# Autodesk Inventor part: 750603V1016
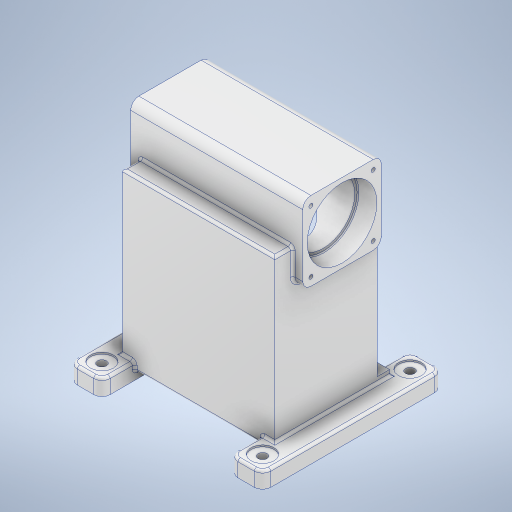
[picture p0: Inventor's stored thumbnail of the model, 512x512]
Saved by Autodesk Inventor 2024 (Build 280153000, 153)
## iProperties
Created: 2025-06
Part Number: 750603V1016
Material: 알루미늄 6061
Document SubType Name: Modeling
Designer: 11
Mass: 8009.62 g
Surface Area: 3457.08 cm^2
Volume: 2966.53 cm^3
Density: 2.7 g/cm^3
Appearance: 알루미늄 - 평지
Author: 11
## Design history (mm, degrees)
sketch "스케치1"
  geometry: L1 (-103, 70)-(103, 70); L2 (103, 70)-(103, -70); L3 (103, -70)-(-103, -70); L4 (-103, -70)-(-103, 70); L5 (103, -55)-(-86, -55); L6 (-86, -55)-(-86, -70); 4 further points
  constraints: 12 end point, 3 midpoint, 3 perpendicular, 2 parallel, 2 point on line, 1 horizontal, 1 horizontal alignment, 1 vertical alignment
  dimensions: "d0" = 206 distance of L2.end L3.end; "d1" = 140 distance of L1.end L2.end; "d8" = 15 distance between parallel lines of L3 L5; "d9" = 189 distance from line of point (-86, -62.5) L2
extrude "돌출1" new body sketch "스케치1" stored distance "d2" = 186; taper "d3" = 0 deg
sketch "스케치2"
  geometry: L1 (211, 180)-(-25, 180); L2 (-25, 180)-(-25, -40); L3 (-25, -40)-(211, -40); L4 (211, -40)-(211, 180); L5 (171, 180)-(171, -40); L6 (15, 180)-(15, -40); 3 further points
  constraints: 12 end point, 4 point on line, 3 perpendicular, 2 midpoint, 2 parallel, 1 horizontal, 1 horizontal alignment, 1 vertical alignment
  dimensions: "d4" = 236 distance of L2.end L3.end; "d10" = 220 distance of L3.end L1.start; "d11" = 40 distance between parallel lines of L2 L6; "d12" = 40 distance between parallel lines of L4 L5
extrude "돌출2" join sketch "스케치2" stored distance "d13" = 20; taper "d14" = 0 deg
sketch "스케치3"
  geometry: L1 (158, 38)-(158, -38); L2 (148, -48)-(72, -48); L3 (62, -38)-(62, 38); L4 (72, 48)-(148, 48); L5 (-113, -110)-(-113, 110) reference; L6 (-93, 70)-(103, 70) reference; L7 (103, 70)-(103, -55) reference; A1 r 10 centre (148, 38) between (158, 38) and (148, 48); A2 r 10 centre (148, -38) between (148, -48) and (158, -38); A3 r 10 centre (72, 38) between (72, 48) and (62, 38); A4 r 10 centre (72, -38) between (62, -38) and (72, -48); 8 further points
  constraints: 8 end point, 8 point on circle, 8 point on line, 8 tangent, 4 centre point, 3 midpoint, 3 perpendicular, 2 equal radius, 1 horizontal alignment, 1 vertical
  dimensions: "d15" = 271 distance between parallel lines of L5 L1; "d16" = 96 distance of point (158, 48) point (158, -48); "d17" = 96 distance of point (158, -48) point (62, -48); "d21" = 10 radius of A1 (derived); "d24" = 10 radius of A3 (derived)
extrude "돌출3" join sketch "스케치3" stored distance "d22" = 210; taper "d23" = 0 deg
node "작업 평면1"
sketch "스케치5"
  geometry: L1 (-12, 32)-(-12, 108) reference; L2 (198, 108)-(198, 32) reference; L3 (198, 22)-(198, 32) reference; L4 (198, 108)-(198, 118) reference; L5 (-12, 118)-(-12, 108) reference; L6 (-12, 32)-(-12, 22) reference; L7 (198, 70)-(-12, 70); L8 (-12, 70)-(-12, 27.5); L9 (11, 28.6)-(11, 31.5); L10 (11, 31.5)-(175, 31.5); L11 (175, 31.5)-(175, 28.6); L12 (186, 32)-(198, 32) reference; L13 (176.1, 27.5)-(198, 27.5); L14 (198, 70)-(198, 27.5); L15 (9.9, 27.5)-(-12, 27.5); L16 (-12, 32)-(0, 32) reference; A1 r 1.1 centre (9.9, 28.6) between (9.9, 27.5) and (11, 28.6); A2 r 1.1 centre (176.1, 28.6) between (175, 28.6) and (176.1, 27.5); 4 further points
  constraints: 16 end point, 5 midpoint, 4 perpendicular, 4 point on circle, 4 tangent, 2 centre point, 2 point on line, 1 equal radius, 1 parallel, 1 vertical
  dimensions: "d39" = 85 diameter of L15 L7; "d40" = 77 diameter of L10 L7; "d41" = 23 distance from line of L8 point (11, 30.05); "d42" = 23 horizontal distance of point (198, 27) point (175, 30.05); "d43" = 85 diameter of L13 L7; "d44" = 1.1 radius of A1 (derived)
revolve "회전2" sketch "스케치5" stored, may be unused: angle "d45" = 90 deg
sketch "스케치7"
  geometry: L1 (-86, -55)-(103, -55) reference; L2 (103, 70)-(-93, 70) reference; L3 (10, 70)-(10, -55); L4 (-113, 110)-(-113, -110) reference; L5 (10, -55)-(96, -55); L6 (96, -55)-(96, 47); L7 (96, 47)-(41, 47); L8 (41, 47)-(41, 62); L9 (40, 63)-(37, 63); L10 (37, 63)-(37, 63); L11 (34, 66)-(10, 66); A1 r 3 centre (34, 63) between (37, 63) and (34, 66); A2 r 1 centre (40, 62) between (41, 62) and (40, 63); 2 further points
  constraints: 16 end point, 6 perpendicular, 4 point on circle, 4 point on line, 4 tangent, 2 centre point, 1 vertical
  dimensions: "d68" = 123 distance between parallel lines of L4 L3; "d70" = 172 diameter of L6 L3; "d71" = 102 distance between parallel lines of L1 L7; "d72" = 16 distance between parallel lines of L7 L9; "d73" = 3 distance between parallel lines of L9 L11; "d74" = 62 diameter of L8 L3; "d75" = 54 diameter of L9.end L3; "d76" = 3 radius of A1 (derived); "d77" = 1 radius of A2
revolve "회전4" sketch "스케치7" stored, may be unused: angle "d78" = 90 deg
chamfer "모따기1" distance "d79" = 1; stored, may be unused: second distance "d80" = 2, angle "d81" = 45 deg
fillet "모깎기3" dims "d82" = 10
sketch "스케치8"
  geometry: L1 (171, -140)-(15, -140) reference; C1 r 14 at (191, -160); C2 r 5.5 at (191, -160); C3 r 14 at (-5, -160); C4 r 5.5 at (-5, -160); C5 r 14 at (191, 20); C6 r 5.5 at (191, 20); C7 r 14 at (-5, 20); C8 r 5.5 at (-5, 20); 2 further points
  constraints: 8 centre point, 6 equal radius, 4 coincident, 2 horizontal alignment, 2 vertical alignment, 1 midpoint
  dimensions: "d83" = 11 diameter of C2; "d84" = 28 diameter of C1; "d85" = 98 horizontal distance of point (93, -140) C1.centre; "d86" = 90 vertical distance of point (93, -70) C1.centre; "d87" = 90 vertical distance of point (93, -70) C5.centre; "d88" = 98 horizontal distance of point (93, -140) C3.centre
extrude "돌출4" cut sketch "스케치8" extent not by distance; stored distance "d89" = 0; taper "d90" = 0 deg
extrude "돌출5" cut sketch "스케치8" distance "d91" = 2; taper "d92" = 0 deg
fillet "모깎기4" dims "d93" = 3
sketch "스케치9"
  geometry: C1 r 42.5 at (0, 110) reference; 5 further points
  constraints: 2 horizontal alignment, 2 vertical alignment
  dimensions: "d101" = 38 horizontal distance of C1.centre point (-38, 147.096); "d102" = 38 horizontal distance of C1.centre point (-38, 72); "d103" = 38 horizontal distance of point (38, 147.096) C1.centre
hole "구멍1" sketch "스케치9" at (-38, 147.096), (38, 147.096), (38, 72), (-38, 72) diameter "d94" = 4.917; stored, may be unused: countersink angle "d98" = 90 deg, drill point angle "d100" = 118 deg; dims "d95" = 12, "d96" = 4, "d97" = 2, "d99" = 14
sketch "스케치10"
  geometry: L1 (186, 0)-(0, 0) reference; L2 (0, -189)-(0, 0) reference; L3 (186, -189)-(0, -189) reference; L4 (186, 0)-(186, -189) reference; C1 r 87 at (93, -93) reference; 5 further points
  constraints: 2 horizontal alignment, 1 vertical alignment
  dimensions: "d113" = 75 horizontal distance of C1.centre point (18, -18); "d114" = 75 horizontal distance of C1.centre point (18, -18); "d115" = 75 horizontal distance of point (18, -168) C1.centre; "d116" = 75 horizontal distance of C1.centre point (18, -168); "d117" = 75 horizontal distance of point (168, -168) C1.centre
  node "투영된 루프1"
hole "구멍2" sketch "스케치10" diameter "d104" = 6.647; stored, may be unused: countersink angle "d108" = 90 deg, drill point angle "d110" = 118 deg; dims "d105" = 16, "d106" = 4, "d107" = 2, "d109" = 18
hole "구멍3" sketch "스케치10" diameter "d118" = 6.647; stored, may be unused: countersink angle "d122" = 90 deg, drill point angle "d124" = 118 deg; dims "d119" = 16, "d120" = 4, "d121" = 2, "d123" = 18
sketch "스케치11"
  geometry: L1 (0, 10)-(210, 10) reference; 2 further points
  constraints: 1 vertical alignment, 1 other
  dimensions: "d125" = 30 distance from line of L1 point (105, -20)
feature "엠보싱1" sketch "스케치11" dims "d0" = 206, "d1" = 140, "d8" = 15, "d9" = 189, "d126" = 0.5, "d127" = 0
node "솔리드1"
mirror "미러1"
feature "A9D066F2-1C7D-4E18-AEED-F7BC21143FA4" dims "d104" = 6.647, "d105" = 16, "d106" = 4, "d107" = 2, "d108" = 90 deg, "d109" = 18, "d110" = 118 deg
other parameters: "d38" = -223
